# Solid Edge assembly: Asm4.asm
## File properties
Author: Deepak Maini
Template: normal.asm
Last saved by: Robert a Rhodes jr
Revision: 1
Application: Solid Edge
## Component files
main assem.asm
arti subassm.asm
link pin.par
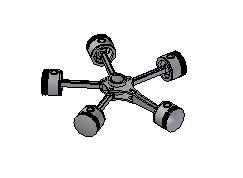
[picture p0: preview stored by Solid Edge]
